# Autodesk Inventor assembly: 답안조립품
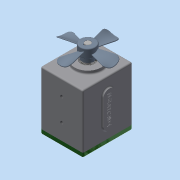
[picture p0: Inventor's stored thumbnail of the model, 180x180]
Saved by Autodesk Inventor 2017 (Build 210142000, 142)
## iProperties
Part Number: 답안조립품
Material: 일반
Document SubType Name: Assembly
Designer: MRC
Author: MRC
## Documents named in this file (17)
- C:\Users\MRC\Desktop\610205V1009\답안조립품.iam
- C:\Users\MRC\Desktop\610205V1009\본체.ipt
- C:\Users\MRC\Desktop\610205V1009\가변스프링.ipt
- C:\Users\MRC\Desktop\610205V1009\멈춤나사 M3x8.ipt
- C:\Users\MRC\Desktop\610205V1009\메인 기어 축.ipt
- C:\Users\MRC\Desktop\610205V1009\베어링 608.ipt
- C:\Users\MRC\Desktop\610205V1009\베어링 6903.ipt
- C:\Users\MRC\Desktop\610205V1009\볼트 M4 x 10.ipt
- C:\Users\MRC\Desktop\610205V1009\부시.ipt
- C:\Users\MRC\Desktop\610205V1009\서브 기어 축.ipt
- C:\Users\MRC\Desktop\610205V1009\슬라이더.ipt
- C:\Users\MRC\Desktop\610205V1009\오일 실 8 22 7.ipt
- C:\Users\MRC\Desktop\610205V1009\오일 실 17 30 8.ipt
- C:\Users\MRC\Desktop\610205V1009\커버.ipt
- C:\Users\MRC\Desktop\610205V1009\키 5 x 5 x 24.ipt
- C:\Users\MRC\Desktop\610205V1009\팬날개.ipt
- 팬날개.ipt
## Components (1 placed, 1 different names)
1. 가변스프링:1
